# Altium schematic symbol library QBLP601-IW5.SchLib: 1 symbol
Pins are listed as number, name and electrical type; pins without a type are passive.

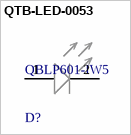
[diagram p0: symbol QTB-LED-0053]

## QTB-LED-0053
designator D?, comment QBLP601-IW5
LED WHITE DIFFUSED 0603 SMD; Manufacturer: QT Brightek (QTB); Lens Size: 0.8mm; Luminous Intensity: 78mcd; Test Current: 5mA; Lens Color: Yellow; Lens Style: Flat; Forward Voltage: 2.8V
footprint FP-QBLP601-IW5-MFG
pins: 1 ANODE (+), 2 CATHODE (-)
